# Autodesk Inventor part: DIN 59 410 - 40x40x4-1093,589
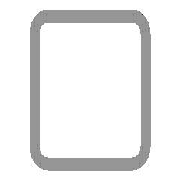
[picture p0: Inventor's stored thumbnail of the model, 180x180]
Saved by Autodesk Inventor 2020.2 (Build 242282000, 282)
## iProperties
Manager: www.cadconsulting.pl
Company: Fabian Stasiak CAD Consulting
_CCFamilyMember: 20
_CCFamilyDisplayName: DIN 59410 (Kwadrat) - Rurki stalowe o przekroju kwadratowym formowane na gorąco
_FrameMemberDoc: Frame Member File
_Version: 15.0.0
_GetPNFromCC: 1
IsCustomPart: 1
Created: 2014-02
Part Number: DIN 59 410 - 40x40x4-1093,589
Material: Stal, miękka
Description: Rurki stalowe o przekroju kwadratowym formowane na gorąco
Document SubType Name: Modellieren
Standard: DIN
Designer: F.Stasiak
Standards Organization: DIN
Language: pl-PL
Size Designation: 40x40x4
Categories: <MemberInstance><Categories><Category DisplayName="Kształtowniki konstrukcyjne" InternalName="089c4875-fa83-4c05-b084-43b9cc11f5ed" Mnemonic="GRDR"><CategoryPar
Stock Number: 40x40x4
Density: 7.85 g/cm^3
Appearance: Częściowo polerowana
Mass: 4393.44 g
Surface Area: 2813.5 cm^2
Volume: 559.674 cm^3
Catalog Web Link: www.expertbooks.pl
G_L: 1093,589 mm
G_W: 40,000 mm
G_H: 40,000 mm
+4027E53C-3DD6-4FB5-8A42-085C22343A6F+CUTDETAIL1: Wytnij
+C1E92D50-59AD-4EBC-869A-7708A109B6D8+CUTDETAIL2: Wytnij
Author: F.Stasiak
Subject: Zbiór ćwiczeń. Autodesk Inventor 2020. Kurs Professional
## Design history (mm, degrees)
node "Płaszczyzna początkowa"
node "Płaszczyzna końcowa"
sketch "Szkic1"
  geometry: L1 (-12, 20)-(12, 20); L2 (20, 12)-(20, -12); L3 (12, -20)-(-12, -20); L4 (-20, -12)-(-20, 12); L5 (-30.32, 0)-(30.32, 0) reference; L6 (0, -30.32)-(0, 30.32) reference; L7 (-12, 16)-(12, 16); L8 (16, 12)-(16, -12); L9 (12, -16)-(-12, -16); L10 (-16, -12)-(-16, 12); A1 r 8 centre (-12, 12) between (-12, 20) and (-20, 12); A2 r 8 centre (12, 12) between (20, 12) and (12, 20); A3 r 8 centre (12, -12) between (12, -20) and (20, -12); A4 r 8 centre (-12, -12) between (-20, -12) and (-12, -20); A5 r 4 centre (-12, 12) between (-12, 16) and (-16, 12); A6 r 4 centre (12, 12) between (16, 12) and (12, 16); A7 r 4 centre (12, -12) between (12, -16) and (16, -12); A8 r 4 centre (-12, -12) between (-16, -12) and (-12, -16); 3 further points
  constraints: 16 end point, 16 point on circle, 8 centre point, 8 tangent, 6 point on line, 4 parallel, 3 equal radius, 3 perpendicular, 1 horizontal, 7 other
  dimensions: "b" = 40 distance of point (-20, 20) point (20, 20); "msp_r" = 8 radius of A1 (= 2 x ParT); "d8" = 20 distance between parallel lines of L4 L6 (= d9); "d9" = 20 distance between parallel lines of L3 L5 (= 0.5 x b); "d10" = 4 distance between parallel lines of L3 L9 (= ParT)
extrude "Bryła" new body sketch "Szkic1" taper "d4" = 0 deg; stored distance "NLG" = 10
node "Driven Length"
  sketch "Sketch2"
    geometry: L1 (0, 0)-(10, 0) reference
    constraints: 2 end point, 1 horizontal
  workplane "Work Plane3"
  sketch "Sketch3"
    geometry: L1 (-2, 22.426)-(12, 22.426) reference; L2 (-2, 1116.016)-(12, 1116.016) reference
    dimensions: "d14" = 1093.5891 distance between parallel lines of L1 L2 (derived)
node "Płaszczyzna konstrukcyjna4"
feature "Podział1"
node "Płaszczyzna konstrukcyjna5"
feature "Podział2"
body "Solid1"
other parameters: "ParT" = 4, "G_OFFSET_START" = -22.42641 [user parameter; used in 1 equation term], "G_OFFSET_END" = -15.35534 [user parameter; used in 1 equation term], "d11" = 22.42641 (= -G_OFFSET_START), "d12" = 1116.01551 (= G_OFFSET_END + B_L), "G_L" = 1093.5891 (= d14) [user parameter], "B_L" = 1131.37085 [user parameter; used in 1 equation term], "d13" = 90 deg
